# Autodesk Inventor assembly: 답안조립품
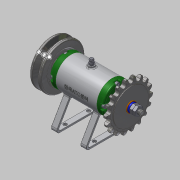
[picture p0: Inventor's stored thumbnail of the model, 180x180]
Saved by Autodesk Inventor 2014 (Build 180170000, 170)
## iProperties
Created: 2016-03
Part Number: 답안조립품
Document SubType Name: Assembly
Designer: SCD-A15
Author: SCD-A15
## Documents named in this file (16)
- C:\Users\SCD-A15\Desktop\460308V1009\답안조립품.iam
- C:\Users\SCD-A15\Desktop\460308V1009\본체.ipt
- C:\Users\SCD-A15\Desktop\460308V1009\축.ipt
- C:\Users\SCD-A15\Desktop\460308V1009\베어링 15 x 32 x 9.ipt
- C:\Users\SCD-A15\Desktop\460308V1009\커버.ipt
- C:\Users\SCD-A15\Desktop\460308V1009\오일 실 15 25 7.ipt
- C:\Users\SCD-A15\Desktop\460308V1009\키 3 x 3 x 12.ipt
- C:\Users\SCD-A15\Desktop\460308V1009\볼트 M4 x 12.ipt
- C:\Users\SCD-A15\Desktop\460308V1009\V벨트풀리.ipt
- C:\Users\SCD-A15\Desktop\460308V1009\스프로킷.ipt
- C:\Users\SCD-A15\Desktop\460308V1009\와셔 8x17.ipt
- C:\Users\SCD-A15\Desktop\460308V1009\스프링와셔 8.ipt
- C:\Users\SCD-A15\Desktop\460308V1009\너트 M 8.ipt
- C:\Users\SCD-A15\Desktop\460308V1009\니플 M 6 x 0.75.ipt
- C:\Users\SCD-A15\Desktop\460308V1009\와셔 6x11.5.ipt
- C:\Users\SCD-A15\Desktop\460308V1009\볼트 M 6 x 8.ipt
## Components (11 placed, 3 different names)
1. KS B 2023 6002 - 15 x 32 x 9:1
2. KS B 2023 6002 - 15 x 32 x 9:2
3. V벨트풀리:1
4. ISO 4762 M4 x 12:2
5. ISO 4762 M4 x 12:3
6. ISO 4762 M4 x 12:4
7. ISO 4762 M4 x 12:5
8. ISO 4762 M4 x 12:1
9. ISO 4762 M4 x 12:6
10. ISO 4762 M4 x 12:7
11. ISO 4762 M4 x 12:8
